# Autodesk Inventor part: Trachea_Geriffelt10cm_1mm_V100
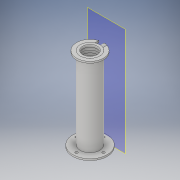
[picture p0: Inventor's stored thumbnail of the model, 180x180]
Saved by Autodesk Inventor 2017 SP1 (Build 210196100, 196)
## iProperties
Part Number: Trachea_Geriffelt10cm_1mm_V100
Material: Generisch
Document SubType Name: Modeling
Designer: haesner
Density: 1 g/cm^3
Appearance: Vorgabe
Part Number: Trachea_Geriffelt10cm_1mm_V100_3D-Druck
Author: haesner
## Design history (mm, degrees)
sketch "Skizze1"
  geometry: L1 (-14.4, 0)-(2.4, 0) reference; L2 (-9, 0)-(-12, 0); L3 (-12, 102)-(-12, 0); L4 (0, -20.4)-(0, 122.4) reference; L5 (-8.5, 0)-(-8.5, 102); L6 (-9.5, 102)-(-9.5, 0); L7 (-9, 102)-(-12, 102); A1 r 2.5 centre (-11, 4.5) between (-9, 3) and (-9, 6); A2 r 2.5 centre (-7, 1.5) between (-9, 3) and (-9, 0); A3 r 2.5 centre (-11, 10.5) between (-9, 9) and (-9, 12); A4 r 2.5 centre (-7, 7.5) between (-9, 9) and (-9, 6); A5 r 2.5 centre (-11, 16.5) between (-9, 15) and (-9, 18); A6 r 2.5 centre (-7, 13.5) between (-9, 15) and (-9, 12); A7 r 2.5 centre (-7, 19.5) between (-9, 21) and (-9, 18); A8 r 2.5 centre (-11, 22.5) between (-9, 21) and (-9, 24); A9 r 2.5 centre (-7, 25.5) between (-9, 27) and (-9, 24); A10 r 2.5 centre (-11, 28.5) between (-9, 27) and (-9, 30); A11 r 2.5 centre (-11, 46.5) between (-9, 45) and (-9, 48); A12 r 2.5 centre (-7, 43.5) between (-9, 45) and (-9, 42); A13 r 2.5 centre (-11, 40.5) between (-9, 39) and (-9, 42); A14 r 2.5 centre (-7, 37.5) between (-9, 39) and (-9, 36); A15 r 2.5 centre (-11, 34.5) between (-9, 33) and (-9, 36); A16 r 2.5 centre (-7, 31.5) between (-9, 33) and (-9, 30); A17 r 2.5 centre (-7, 49.5) between (-9, 51) and (-9, 48); A18 r 2.5 centre (-11, 52.5) between (-9, 51) and (-9, 54); A19 r 2.5 centre (-7, 55.5) between (-9, 57) and (-9, 54); A20 r 2.5 centre (-11, 58.5) between (-9, 57) and (-9, 60); A21 r 2.5 centre (-11, 70.5) between (-9, 69) and (-9, 72); A22 r 2.5 centre (-7, 67.5) between (-9, 69) and (-9, 66); A23 r 2.5 centre (-11, 64.5) between (-9, 63) and (-9, 66); A24 r 2.5 centre (-7, 61.5) between (-9, 63) and (-9, 60); A25 r 2.5 centre (-7, 85.5) between (-9, 87) and (-9, 84); A26 r 2.5 centre (-11, 76.5) between (-9, 75) and (-9, 78); A27 r 2.5 centre (-7, 73.5) between (-9, 75) and (-9, 72); A28 r 2.5 centre (-11, 82.5) between (-9, 81) and (-9, 84); A29 r 2.5 centre (-7, 79.5) between (-9, 81) and (-9, 78); A30 r 2.5 centre (-11, 88.5) between (-9, 87) and (-9, 90); A31 r 2.5 centre (-7, 91.5) between (-8.394, 93.576) and (-9, 90); A32 r 2.5 centre (-11, 94.5) between (-9, 93) and (-9, 96); A33 r 2.5 centre (-7, 97.5) between (-9, 99) and (-9, 96); A34 r 2.5 centre (-11, 100.5) between (-9, 99) and (-9, 102); 2 further points
  constraints: 69 point on circle, 34 centre point, 33 tangent, 19 equal radius, 10 end point, 5 point on line, 2 vertical, 1 horizontal, 1 horizontal alignment, 1 perpendicular, 37 other
  dimensions: "d4" = 3 distance of A1.start L2.start; "d5" = 3 distance of A1.end A3.start; "d6" = 3 distance of A3.end A5.start; "d11" = 3 distance of A5.end A7.start; "d12" = 3 distance of A8.end A9.start; "d20" = 3 distance of A10.end A15.start; "d21" = 3 distance of A14.end A13.start; "d22" = 3 distance of A12.end A11.start; "d27" = 3 distance of A11.end A17.start; "d28" = 3 distance of A18.end A19.start; "d31" = 3 distance of A20.end A23.start; "d32" = 3 distance of A22.end A21.start; "d33" = 3 distance of A21.end A26.start; "d34" = 3 distance of A26.end A28.start; "d35" = 3 distance of A25.end A25.start; "d89" = 12 distance from line of point (0, 0) L3; "d96" = 9 dimension on L4; "d97" = 102 distance of L3.start L2.end; "d119" = 8.5 distance between parallel lines of L4 L5; "d125" = 9.5 distance between parallel lines of L4 L6
revolve "Umdrehung2" sketch "Skizze1" stored, may be unused: angle "d121" = 90 deg
sketch "Skizze2"
  geometry: C1 r 21 at (0, 0); C2 r 12 at (0, 0); 1 further point
  constraints: 2 centre point, 1 coincident
  dimensions: "d44" = 42 diameter of C1
extrude "Extrusion1" join sketch "Skizze2" distance "d45" = 2; taper "d46" = 0 deg
workplane "Arbeitsebene2"
sketch "Skizze9"
  geometry: L1 (5, 10.909)-(5, 15.724); L2 (-5, 15.724)-(-5, 10.909); L3 (-23.1, 0)-(23.1, 0); L4 (0, -22.945)-(0, 22.169); A1 r 16.5 centre (0, 0) between (-5, 15.724) and (5, 15.724); A2 r 12 centre (0, 0) between (-5, 10.909) and (5, 10.909); 1 further point
  constraints: 8 end point, 4 point on circle, 2 centre point, 1 coincident, 1 parallel, 1 other
  dimensions: "d90" = 33 diameter of A1; "d108" = 10 distance between parallel lines of L1 L2; "d109" = 12 radius of A2; "d110" = 16.5 radius of A1 (derived)
extrude "Extrusion6" join sketch "Skizze9" distance "d91" = 2; taper "d92" = 0 deg
sketch "Skizze10"
  geometry: L1 (0, -20)-(0, 120) reference; L2 (4.2, 0)-(-4.2, 0) reference; C1 r 3 at (0, 97); 1 further point
  constraints: 1 centre point, 1 point on line
  dimensions: "d98" = 6 diameter of C1; "d99" = 97 distance from line of L2 C1.centre
extrude "Extrusion10" cut sketch "Skizze10" distance "d122" = 9; taper "d123" = 0 deg
sketch "Skizze11"
  geometry: 2 further points
  constraints: 1 other
extrude "Extrusion8" join sketch "Skizze11" distance "d102" = 8; taper "d103" = 0 deg
sketch "Skizze12"
  geometry: L1 (3, 0)-(-3, 0); L2 (-2.236, -2)-(2.236, -2); C1 r 0.75 at (0, 0); A1 r 3 centre (0, 0) between (-2.236, -2) and (2.236, -2); A2 r 3 centre (0, 0) between (3, 0) and (-3, 0); 1 further point
  constraints: 4 end point, 4 point on circle, 3 centre point, 1 coincident
  dimensions: "d104" = 1.5 diameter of C1
extrude "Extrusion9" cut sketch "Skizze12" distance "d105" = 18; taper "d106" = 0 deg
sketch "Skizze13"
  geometry: L1 (0, 16.5)-(-16.5, 0); L2 (-16.5, 0)-(0, -16.5); L3 (0, -16.5)-(16.5, 0); L4 (16.5, 0)-(0, 16.5); L5 (37.479, 0)-(-30.746, 0); L6 (0, -39.011)-(0, 31.002); 1 further point
  constraints: 12 end point, 3 point on line, 2 parallel, 2 perpendicular
  dimensions: "d111" = 16.5 distance from line of L5 L1.start
hole "Bohrung3" sketch "Skizze13" diameter "d112" = 3; stored, may be unused: countersink angle "d116" = 90 deg, drill point angle "d118" = 118 deg; dims "d113" = 6, "d114" = 4, "d115" = 2, "d117" = 8
fillet "Rundung2" dims "d124" = 0.5
node "Volumenkörper1"
node "Volumenkörper2"
